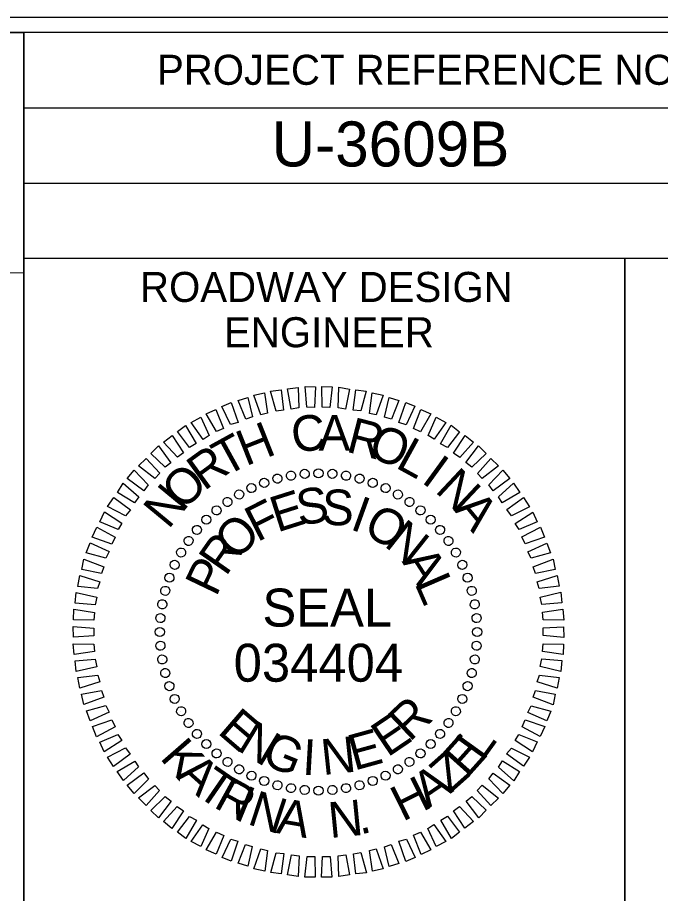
# Model space of a CAD drawing. Extents: x 2320980 to 2456309, y 595047 to 606177.
# Drawn here: x 2456001.89 to 2456023.3, y 596927.41 to 596956.57 of the extents above; entities that cross this region are included whole.
import ezdxf

# ---------------------------------------------------------------- set-up
doc = ezdxf.new("R2010")
doc.units = 0
for name, color, linetype in [('Scratch_Level_0', 7, 'Continuous'), ('Sheet Data Field CELL', 7, 'Continuous'), ('Sheet Plan CELL', 7, 'Continuous'), ('Sheet Plot Border Inside CELL', 7, 'Continuous')]:
    doc.layers.add(name, color=color, linetype=linetype)

msp = doc.modelspace()

# ---------------------------------------------------------------- linework, layer by layer
at = {"layer": 'Scratch_Level_0'}
msp.add_lwpolyline([(2455979.323, 596956.076), (2456002.097, 596956.079), (2456002.098, 596948.07), (2455979.324, 596948.067)], close=True, dxfattribs=at)
at = {"layer": 'Sheet Data Field CELL'}
for p, q in [((2456011.001, 596941.316), (2456011.001, 596941.316)), ((2456011.453, 596941.387), (2456011.453, 596941.387)), ((2456011.916, 596941.406), (2456011.916, 596941.406)), ((2456012.38, 596941.383), (2456012.38, 596941.383)), ((2456012.834, 596941.317), (2456012.834, 596941.317)), ((2456010.099, 596941.09), (2456010.099, 596941.09)), ((2456010.539, 596941.224), (2456010.539, 596941.224)), ((2456013.278, 596941.23), (2456013.278, 596941.23)), ((2456013.722, 596941.09), (2456013.722, 596941.09)), ((2456009.274, 596940.696), (2456009.274, 596940.696)), ((2456009.681, 596940.914), (2456009.681, 596940.914)), ((2456014.147, 596940.908), (2456014.147, 596940.908)), ((2456014.561, 596940.704), (2456014.561, 596940.704)), ((2456008.878, 596940.447), (2456008.878, 596940.447)), ((2456014.945, 596940.448), (2456014.945, 596940.448)), ((2456008.514, 596940.177), (2456008.514, 596940.177)), ((2456015.319, 596940.17), (2456015.319, 596940.17)), ((2456008.172, 596939.855), (2456008.172, 596939.855)), ((2456015.65, 596939.86), (2456015.65, 596939.86)), ((2456007.862, 596939.523), (2456007.862, 596939.523)), ((2456015.972, 596939.518), (2456015.972, 596939.518)), ((2456007.584, 596939.15), (2456007.584, 596939.15)), ((2456016.242, 596939.154), (2456016.242, 596939.154)), ((2456007.327, 596938.766), (2456007.327, 596938.766)), ((2456016.491, 596938.758), (2456016.491, 596938.758)), ((2456007.124, 596938.352), (2456007.124, 596938.352)), ((2456016.709, 596938.351), (2456016.709, 596938.351)), ((2456006.941, 596937.927), (2456006.941, 596937.927)), ((2456016.885, 596937.932), (2456016.885, 596937.932)), ((2456006.802, 596937.483), (2456006.802, 596937.483)), ((2456017.019, 596937.492), (2456017.019, 596937.492)), ((2456006.715, 596937.039), (2456006.715, 596937.039)), ((2456017.111, 596937.031), (2456017.111, 596937.031)), ((2456006.649, 596936.585), (2456006.649, 596936.585)), ((2456017.183, 596936.579), (2456017.183, 596936.579)), ((2456006.625, 596936.121), (2456006.625, 596936.121)), ((2456017.201, 596936.116), (2456017.201, 596936.116)), ((2456006.644, 596935.658), (2456006.644, 596935.658)), ((2456017.178, 596935.652), (2456017.178, 596935.652)), ((2456006.715, 596935.206), (2456006.715, 596935.206)), ((2456017.112, 596935.198), (2456017.112, 596935.198)), ((2456006.807, 596934.744), (2456006.807, 596934.744)), ((2456017.025, 596934.754), (2456017.025, 596934.754)), ((2456006.942, 596934.304), (2456006.942, 596934.304)), ((2456016.885, 596934.309), (2456016.885, 596934.309)), ((2456007.117, 596933.886), (2456007.117, 596933.886)), ((2456016.703, 596933.884), (2456016.703, 596933.884)), ((2456007.335, 596933.479), (2456007.335, 596933.479)), ((2456016.499, 596933.47), (2456016.499, 596933.47)), ((2456007.584, 596933.083), (2456007.584, 596933.083)), ((2456016.243, 596933.086), (2456016.243, 596933.086)), ((2456007.854, 596932.719), (2456007.854, 596932.719)), ((2456015.965, 596932.713), (2456015.965, 596932.713)), ((2456008.176, 596932.377), (2456008.176, 596932.377)), ((2456015.655, 596932.381), (2456015.655, 596932.381)), ((2456008.508, 596932.067), (2456008.508, 596932.067)), ((2456015.313, 596932.059), (2456015.313, 596932.059)), ((2456008.881, 596931.789), (2456008.881, 596931.789)), ((2456014.949, 596931.789), (2456014.949, 596931.789)), ((2456009.265, 596931.532), (2456009.265, 596931.532)), ((2456014.553, 596931.54), (2456014.553, 596931.54)), ((2456009.679, 596931.329), (2456009.679, 596931.329)), ((2456010.104, 596931.146), (2456010.104, 596931.146)), ((2456013.728, 596931.146), (2456013.728, 596931.146)), ((2456014.146, 596931.322), (2456014.146, 596931.322)), ((2456010.549, 596931.007), (2456010.549, 596931.007)), ((2456010.993, 596930.92), (2456010.993, 596930.92)), ((2456011.447, 596930.854), (2456011.447, 596930.854)), ((2456011.911, 596930.83), (2456011.911, 596930.83)), ((2456012.374, 596930.849), (2456012.374, 596930.849)), ((2456012.826, 596930.92), (2456012.826, 596930.92)), ((2456013.287, 596931.012), (2456013.287, 596931.012))]:
    msp.add_line(p, q, dxfattribs=at)
for points in [[(2456011.004, 596943.539), (2456010.877, 596944.211), (2456011.234, 596944.259), (2456011.256, 596943.575)], [(2456011.53, 596943.601), (2456011.465, 596944.284), (2456011.813, 596944.28), (2456011.783, 596943.595)], [(2456012.035, 596943.599), (2456012.023, 596944.284), (2456012.371, 596944.279), (2456012.288, 596943.593)], [(2456012.563, 596943.577), (2456012.593, 596944.262), (2456012.941, 596944.205), (2456012.816, 596943.539)], [(2456009.493, 596943.197), (2456009.24, 596943.824), (2456009.565, 596943.924), (2456009.713, 596943.274)], [(2456009.996, 596943.342), (2456009.764, 596944.002), (2456010.12, 596944.082), (2456010.217, 596943.399)], [(2456010.5, 596943.467), (2456010.32, 596944.138), (2456010.667, 596944.176), (2456010.752, 596943.503)], [(2456013.07, 596943.501), (2456013.152, 596944.177), (2456013.501, 596944.13), (2456013.323, 596943.474)], [(2456013.609, 596943.395), (2456013.702, 596944.081), (2456014.061, 596944.003), (2456013.831, 596943.346)], [(2456014.116, 596943.267), (2456014.263, 596943.922), (2456014.591, 596943.823), (2456014.339, 596943.197)], [(2456008.98, 596943.019), (2456008.696, 596943.625), (2456009.01, 596943.757), (2456009.243, 596943.087)], [(2456014.593, 596943.085), (2456014.824, 596943.753), (2456015.121, 596943.632), (2456014.837, 596943.016)], [(2456008.521, 596942.79), (2456008.174, 596943.374), (2456008.497, 596943.527), (2456008.751, 596942.889)], [(2456015.071, 596942.894), (2456015.323, 596943.519), (2456015.652, 596943.378), (2456015.305, 596942.782)], [(2456008.073, 596942.529), (2456007.673, 596943.091), (2456007.996, 596943.265), (2456008.27, 596942.659)], [(2456015.559, 596942.66), (2456015.833, 596943.265), (2456016.152, 596943.092), (2456015.762, 596942.537)], [(2456007.614, 596942.258), (2456007.215, 596942.788), (2456007.485, 596942.993), (2456007.843, 596942.388)], [(2456015.975, 596942.383), (2456016.333, 596943), (2456016.611, 596942.784), (2456016.209, 596942.26)], [(2456007.219, 596941.935), (2456006.757, 596942.433), (2456007.038, 596942.659), (2456007.417, 596942.075)], [(2456016.412, 596942.074), (2456016.792, 596942.66), (2456017.07, 596942.433), (2456016.615, 596941.93)], [(2456006.804, 596941.601), (2456006.332, 596942.056), (2456006.581, 596942.314), (2456007.001, 596941.752)], [(2456016.818, 596941.755), (2456017.24, 596942.31), (2456017.498, 596942.062), (2456017.021, 596941.6)], [(2456006.463, 596941.226), (2456005.918, 596941.649), (2456006.177, 596941.896), (2456006.628, 596941.398)], [(2456017.204, 596941.393), (2456017.648, 596941.896), (2456017.905, 596941.647), (2456017.365, 596941.227)], [(2456006.101, 596940.82), (2456005.546, 596941.221), (2456005.773, 596941.499), (2456006.245, 596941.012)], [(2456017.579, 596941.02), (2456018.055, 596941.503), (2456018.281, 596941.222), (2456017.73, 596940.812)], [(2456005.792, 596940.414), (2456005.217, 596940.762), (2456005.412, 596941.071), (2456005.926, 596940.617)], [(2456017.902, 596940.615), (2456018.41, 596941.066), (2456018.616, 596940.764), (2456018.032, 596940.417)], [(2456005.484, 596939.988), (2456004.888, 596940.293), (2456005.094, 596940.592), (2456005.649, 596940.18)], [(2456018.183, 596940.188), (2456018.734, 596940.598), (2456018.94, 596940.286), (2456018.334, 596939.98)], [(2456005.239, 596939.53), (2456004.634, 596939.783), (2456004.786, 596940.112), (2456005.362, 596939.733)], [(2456018.465, 596939.73), (2456019.048, 596940.108), (2456019.191, 596939.784), (2456018.595, 596939.532)], [(2456005.037, 596939.042), (2456004.379, 596939.273), (2456004.532, 596939.602), (2456005.138, 596939.276)], [(2456018.684, 596939.281), (2456019.299, 596939.607), (2456019.442, 596939.273), (2456018.793, 596939.051)], [(2456004.834, 596938.575), (2456004.178, 596938.753), (2456004.309, 596939.082), (2456004.946, 596938.798)], [(2456018.882, 596938.789), (2456019.519, 596939.074), (2456019.641, 596938.749), (2456018.991, 596938.57)], [(2456004.685, 596938.067), (2456004.03, 596938.193), (2456004.097, 596938.541), (2456004.765, 596938.29)], [(2456019.059, 596938.286), (2456019.729, 596938.54), (2456019.798, 596938.194), (2456019.137, 596938.067)], [(2456004.557, 596937.559), (2456003.902, 596937.632), (2456003.97, 596937.991), (2456004.637, 596937.782)], [(2456019.194, 596937.783), (2456019.854, 596937.995), (2456019.924, 596937.638), (2456019.261, 596937.563)], [(2456004.482, 596937.021), (2456003.807, 596937.072), (2456003.843, 596937.431), (2456004.53, 596937.274)], [(2456019.298, 596937.279), (2456019.98, 596937.439), (2456020.018, 596937.081), (2456019.345, 596937.027)], [(2456004.438, 596936.514), (2456003.753, 596936.523), (2456003.768, 596936.871), (2456004.455, 596936.767)], [(2456019.37, 596936.775), (2456020.053, 596936.871), (2456020.08, 596936.514), (2456019.395, 596936.523)], [(2456004.437, 596935.988), (2456003.753, 596935.944), (2456003.747, 596936.302), (2456004.432, 596936.24)], [(2456019.39, 596936.249), (2456020.074, 596936.292), (2456020.08, 596935.934), (2456019.394, 596935.996)], [(2456004.456, 596935.461), (2456003.774, 596935.365), (2456003.746, 596935.723), (2456004.431, 596935.714)], [(2456019.388, 596935.722), (2456020.073, 596935.713), (2456020.058, 596935.365), (2456019.372, 596935.469)], [(2456004.529, 596934.957), (2456003.847, 596934.798), (2456003.809, 596935.155), (2456004.482, 596935.209)], [(2456019.344, 596935.216), (2456020.02, 596935.164), (2456019.984, 596934.805), (2456019.296, 596934.962)], [(2456004.632, 596934.453), (2456003.972, 596934.242), (2456003.903, 596934.598), (2456004.565, 596934.673)], [(2456019.27, 596934.677), (2456019.924, 596934.604), (2456019.856, 596934.245), (2456019.189, 596934.454)], [(2456004.767, 596933.95), (2456004.098, 596933.696), (2456004.028, 596934.042), (2456004.69, 596934.17)], [(2456019.142, 596934.169), (2456019.797, 596934.044), (2456019.729, 596933.695), (2456019.061, 596933.947)], [(2456004.945, 596933.447), (2456004.307, 596933.162), (2456004.186, 596933.487), (2456004.835, 596933.667)], [(2456018.992, 596933.661), (2456019.649, 596933.483), (2456019.517, 596933.154), (2456018.88, 596933.438)], [(2456005.143, 596932.956), (2456004.527, 596932.629), (2456004.384, 596932.964), (2456005.033, 596933.186)], [(2456018.79, 596933.194), (2456019.447, 596932.963), (2456019.295, 596932.634), (2456018.689, 596932.961)], [(2456005.361, 596932.507), (2456004.778, 596932.128), (2456004.635, 596932.452), (2456005.231, 596932.705)], [(2456018.588, 596932.706), (2456019.193, 596932.453), (2456019.04, 596932.124), (2456018.465, 596932.504)], [(2456005.643, 596932.048), (2456005.092, 596931.638), (2456004.886, 596931.951), (2456005.492, 596932.256)], [(2456018.343, 596932.249), (2456018.938, 596931.943), (2456018.733, 596931.645), (2456018.178, 596932.056)], [(2456005.924, 596931.621), (2456005.416, 596931.17), (2456005.211, 596931.472), (2456005.795, 596931.819)], [(2456018.034, 596931.822), (2456018.609, 596931.474), (2456018.415, 596931.165), (2456017.901, 596931.62)], [(2456006.248, 596931.216), (2456005.771, 596930.734), (2456005.545, 596931.014), (2456006.096, 596931.424)], [(2456017.725, 596931.416), (2456018.28, 596931.015), (2456018.053, 596930.737), (2456017.581, 596931.224)], [(2456006.623, 596930.843), (2456006.179, 596930.341), (2456005.921, 596930.589), (2456006.462, 596931.009)], [(2456017.364, 596931.01), (2456017.909, 596930.587), (2456017.649, 596930.341), (2456017.198, 596930.838)], [(2456007.008, 596930.481), (2456006.586, 596929.926), (2456006.329, 596930.175), (2456006.805, 596930.636)], [(2456017.023, 596930.635), (2456017.494, 596930.18), (2456017.246, 596929.923), (2456016.825, 596930.484)], [(2456007.414, 596930.162), (2456007.035, 596929.576), (2456006.757, 596929.803), (2456007.212, 596930.306)], [(2456016.607, 596930.301), (2456017.069, 596929.804), (2456016.788, 596929.578), (2456016.41, 596930.161)], [(2456007.851, 596929.854), (2456007.493, 596929.236), (2456007.216, 596929.453), (2456007.617, 596929.976)], [(2456016.213, 596929.979), (2456016.612, 596929.448), (2456016.341, 596929.243), (2456015.983, 596929.848)], [(2456008.267, 596929.577), (2456007.993, 596928.971), (2456007.674, 596929.145), (2456008.065, 596929.699)], [(2456015.754, 596929.707), (2456016.154, 596929.145), (2456015.83, 596928.971), (2456015.556, 596929.577)], [(2456008.756, 596929.343), (2456008.503, 596928.717), (2456008.174, 596928.859), (2456008.522, 596929.455)], [(2456015.306, 596929.446), (2456015.653, 596928.863), (2456015.329, 596928.71), (2456015.076, 596929.348)], [(2456009.233, 596929.151), (2456009.002, 596928.483), (2456008.705, 596928.604), (2456008.989, 596929.22)], [(2456009.71, 596928.97), (2456009.564, 596928.314), (2456009.235, 596928.414), (2456009.488, 596929.039)], [(2456014.333, 596929.04), (2456014.586, 596928.412), (2456014.262, 596928.312), (2456014.113, 596928.962)], [(2456014.846, 596929.217), (2456015.131, 596928.611), (2456014.817, 596928.479), (2456014.584, 596929.149)], [(2456010.218, 596928.842), (2456010.125, 596928.155), (2456009.765, 596928.233), (2456009.996, 596928.89)], [(2456010.757, 596928.735), (2456010.674, 596928.06), (2456010.326, 596928.106), (2456010.504, 596928.762)], [(2456013.327, 596928.769), (2456013.507, 596928.098), (2456013.16, 596928.061), (2456013.074, 596928.733)], [(2456013.83, 596928.894), (2456014.063, 596928.235), (2456013.706, 596928.155), (2456013.61, 596928.838)], [(2456011.264, 596928.66), (2456011.234, 596927.975), (2456010.885, 596928.032), (2456011.01, 596928.697)], [(2456011.791, 596928.637), (2456011.803, 596927.953), (2456011.455, 596927.957), (2456011.538, 596928.643)], [(2456012.297, 596928.636), (2456012.361, 596927.952), (2456012.014, 596927.957), (2456012.044, 596928.642)], [(2456012.822, 596928.697), (2456012.95, 596928.026), (2456012.593, 596927.977), (2456012.57, 596928.661)]]:
    msp.add_lwpolyline(points, close=True, dxfattribs=at)
for centre, major_axis in [((2456010.546, 596941.221), (-0.039, 0.146)), ((2456010.996, 596941.321), (-0.026, 0.149)), ((2456011.453, 596941.381), (-0.013, 0.151)), ((2456011.913, 596941.401), (0, 0.152)), ((2456012.374, 596941.381), (0.013, 0.151)), ((2456012.831, 596941.321), (0.026, 0.149)), ((2456013.281, 596941.221), (0.039, 0.146)), ((2456009.681, 596940.906), (-0.064, 0.137)), ((2456010.106, 596941.082), (-0.052, 0.143)), ((2456013.72, 596941.082), (0.052, 0.143)), ((2456014.146, 596940.906), (0.064, 0.137)), ((2456009.272, 596940.693), (-0.076, 0.131)), ((2456014.555, 596940.693), (0.076, 0.131)), ((2456008.883, 596940.446), (-0.087, 0.124)), ((2456014.943, 596940.446), (0.087, 0.124)), ((2456008.518, 596940.165), (-0.097, 0.116)), ((2456015.309, 596940.165), (0.097, 0.116)), ((2456008.178, 596939.854), (-0.107, 0.107)), ((2456015.649, 596939.854), (0.107, 0.107)), ((2456007.866, 596939.514), (-0.116, 0.097)), ((2456015.96, 596939.514), (0.116, 0.097)), ((2456007.586, 596939.148), (-0.124, 0.087)), ((2456016.241, 596939.148), (0.124, 0.087)), ((2456007.338, 596938.76), (-0.131, 0.076)), ((2456016.488, 596938.76), (0.131, 0.076)), ((2456007.125, 596938.351), (-0.137, 0.064)), ((2456016.701, 596938.351), (0.137, 0.064)), ((2456006.949, 596937.925), (-0.143, 0.052)), ((2456016.877, 596937.925), (0.143, 0.052)), ((2456006.81, 596937.485), (-0.146, 0.039)), ((2456017.016, 596937.485), (0.146, 0.039)), ((2456006.711, 596937.035), (-0.149, 0.026)), ((2456017.116, 596937.035), (0.149, 0.026)), ((2456006.651, 596936.579), (-0.151, 0.013)), ((2456017.176, 596936.579), (0.151, 0.013)), ((2456006.63, 596936.118), (-0.152, 0)), ((2456017.196, 596936.118), (0.152, 0)), ((2456006.651, 596935.658), (-0.151, -0.013)), ((2456017.176, 596935.658), (0.151, -0.013)), ((2456006.711, 596935.201), (-0.149, -0.026)), ((2456017.116, 596935.201), (0.149, -0.026)), ((2456006.81, 596934.751), (-0.146, -0.039)), ((2456017.016, 596934.751), (0.146, -0.039)), ((2456006.949, 596934.311), (-0.143, -0.052)), ((2456016.877, 596934.311), (0.143, -0.052)), ((2456007.125, 596933.886), (-0.137, -0.064)), ((2456016.701, 596933.886), (0.137, -0.064)), ((2456007.338, 596933.477), (-0.131, -0.076)), ((2456016.488, 596933.477), (0.131, -0.076)), ((2456007.586, 596933.088), (-0.124, -0.087)), ((2456016.241, 596933.088), (0.124, -0.087)), ((2456007.866, 596932.722), (-0.116, -0.097)), ((2456015.96, 596932.722), (0.116, -0.097)), ((2456008.178, 596932.383), (-0.107, -0.107)), ((2456015.649, 596932.383), (0.107, -0.107)), ((2456008.518, 596932.071), (-0.097, -0.116)), ((2456015.309, 596932.071), (0.097, -0.116)), ((2456008.883, 596931.791), (-0.087, -0.124)), ((2456014.943, 596931.791), (0.087, -0.124)), ((2456009.272, 596931.543), (-0.076, -0.131)), ((2456014.555, 596931.543), (0.076, -0.131)), ((2456009.681, 596931.33), (-0.064, -0.137)), ((2456014.146, 596931.33), (0.064, -0.137)), ((2456010.106, 596931.154), (-0.052, -0.143)), ((2456010.546, 596931.015), (-0.039, -0.146)), ((2456010.996, 596930.916), (-0.026, -0.149)), ((2456012.831, 596930.916), (0.026, -0.149)), ((2456013.281, 596931.015), (0.039, -0.146)), ((2456013.72, 596931.154), (0.052, -0.143)), ((2456011.453, 596930.855), (-0.013, -0.151)), ((2456011.913, 596930.835), (0, -0.152)), ((2456012.374, 596930.855), (0.013, -0.151))]:
    msp.add_ellipse(centre, major_axis=major_axis, ratio=0.999708, dxfattribs=at)
at = {"layer": 'Sheet Plan CELL'}
for p, q in [((2456002.097, 596948.564), (2456002.097, 596956.079)), ((2456002.094, 596953.569), (2456042.104, 596953.566)), ((2456002.097, 596951.061), (2456042.104, 596951.066))]:
    msp.add_line(p, q, dxfattribs=at)
for points in [[(2455742.104, 596746.076), (2455742.099, 596956.071), (2456002.097, 596956.079), (2456002.099, 596926.066), (2456042.107, 596926.064), (2456042.107, 596746.076)], [(2456042.112, 596956.076), (2455742.104, 596956.076), (2455742.104, 596746.076), (2456042.107, 596746.076)], [(2456002.097, 596948.564), (2456022.107, 596948.564), (2456022.107, 596926.061), (2456002.099, 596926.066)], [(2456022.107, 596948.564), (2456042.104, 596948.566), (2456042.107, 596926.064), (2456022.107, 596926.061)]]:
    msp.add_lwpolyline(points, close=True, dxfattribs=at)
at = {"layer": 'Sheet Plot Border Inside CELL'}
msp.add_lwpolyline([(2455711.407, 596745.574), (2456044.604, 596745.576), (2456044.607, 596956.574), (2455711.407, 596956.574)], close=True, dxfattribs=at)

# ---------------------------------------------------------------- texts
at = {"layer": 'Sheet Data Field CELL'}
for s, height, rotation, p in [('U-3609B', 1.5, 0, (2456010.352, 596951.614)), ('C', 1.188, 7.2199, (2456011.082, 596942.076)), ('A', 1.187, 0.0203, (2456011.913, 596942.154)), ('H', 1.188, 21.6195, (2456009.489, 596941.627)), ('R', 1.188, 345.6211, (2456012.798, 596942.127)), ('T', 1.188, 28.8198, (2456008.811, 596941.267)), ('O', 1.187, 338.4212, (2456013.507, 596941.981)), ('L', 1.188, 331.2209, (2456014.44, 596941.608)), ('R', 1.188, 36.0205, (2456008.103, 596940.792)), ('I', 1.188, 324.0201, (2456015.302, 596941.117)), ('O', 1.188, 43.2217, (2456007.388, 596940.126)), ('N', 1.188, 316.8189, (2456015.761, 596940.799)), ('N', 1.188, 50.4235, (2456006.914, 596939.507)), ('E', 1.188, 17.6111, (2456010.539, 596939.423)), ('S', 1.188, 8.2556, (2456011.262, 596939.657)), ('S', 1.188, 358.9004, (2456012.02, 596939.68)), ('F', 1.187, 26.967, (2456009.871, 596939.095)), ('I', 1.188, 340.1896, (2456012.928, 596939.549)), ('A', 1.188, 309.6172, (2456016.393, 596940.188)), ('O', 1.187, 330.8335, (2456013.352, 596939.409)), ('O', 1.188, 45.6812, (2456009.186, 596938.462)), ('N', 1.188, 321.4766, (2456014.064, 596939)), ('R', 1.188, 55.0397, (2456008.827, 596937.939)), ('A', 1.188, 302.7603, (2456014.674, 596938.463)), ('P', 1.188, 64.3989, (2456008.502, 596937.259)), ('L', 1.188, 293.4009, (2456015.098, 596937.743)), ('SEAL', 1.2634, 0, (2456010.046, 596936.296)), ('034404', 1.2638, 0, (2456009.089, 596934.46)), ('R', 1.188, 43.4814, (2456014.948, 596932.432)), ('E', 1.188, 319.2769, (2456008.517, 596932.762)), ('E', 1.188, 34.1241, (2456014.209, 596931.924)), ('N', 1.188, 328.634, (2456009.159, 596932.204)), ('E', 1.188, 15.4118, (2456013.1, 596931.494)), ('K', 1.188, 311.168, (2456006.605, 596931.914)), ('G', 1.188, 337.9902, (2456009.967, 596931.744)), ('I', 1.188, 356.7012, (2456011.354, 596931.368)), ('N', 1.188, 6.0564, (2456012.06, 596931.349)), ('E', 1.188, 48.1243, (2456016.869, 596931.232)), ('L', 1.188, 54.2991, (2456017.366, 596931.78)), ('Z', 1.188, 41.5848, (2456016.281, 596930.714)), ('A', 1.188, 318.0722, (2456007.149, 596931.292)), ('T', 1.188, 325.3219, (2456007.797, 596930.713)), ('A', 1.188, 34.3351, (2456015.565, 596930.222)), ('R', 1.188, 331.3047, (2456008.384, 596930.301)), ('H', 1.188, 26.3751, (2456014.715, 596929.79)), ('I', 1.188, 337.7098, (2456009.055, 596929.929)), ('N', 1.188, 341.8307, (2456009.508, 596929.731)), ('A', 1.188, 350.2514, (2456010.47, 596929.429)), ('N', 1.188, 5.5954, (2456012.296, 596929.252)), ('.', 1.188, 14.016, (2456013.299, 596929.364))]:
    msp.add_text(s, height=height, rotation=rotation, dxfattribs=at).set_placement(p)
at = {"layer": 'Sheet Plan CELL'}
for s, height, p in [('PROJECT REFERENCE NO.', 1.00002, (2456006.537, 596954.334)), ('ROADWAY DESIGN', 1.00002, (2456005.972, 596947.104)), ('ENGINEER', 1, (2456008.769, 596945.596))]:
    msp.add_text(s, height=height, rotation=0, dxfattribs=at).set_placement(p)

doc.saveas('drawing.dxf')
